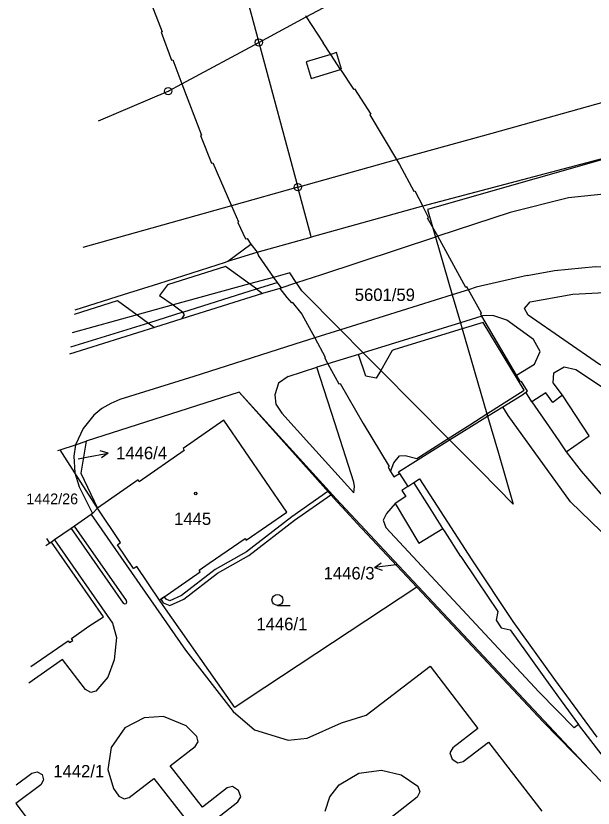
# Model space of a CAD drawing. Extents: x -821458 to -820266, y -1071458 to -1069826.
# Drawn here: x -821457.2 to -821378.4, y -1070339.6 to -1070231.3 of the extents above; entities that cross this region are included whole.
import ezdxf

# ---------------------------------------------------------------- set-up
doc = ezdxf.new("R2010")
doc.units = 0
for name, color, linetype in [('Vrstva 1', 7, 'Continuous'), ('Vrstva 13', 7, 'Continuous'), ('Vrstva 2', 7, 'Continuous'), ('Vrstva 3', 7, 'Continuous'), ('Vrstva 4', 7, 'Continuous'), ('Vrstva 5', 7, 'Continuous'), ('Vrstva 7', 7, 'Continuous'), ('Vrstva 8', 7, 'Continuous')]:
    doc.layers.add(name, color=color, linetype=linetype)

msp = doc.modelspace()

# ---------------------------------------------------------------- linework, layer by layer
at = {"layer": 'Vrstva 1'}
for p, q in [((-821424.05, -1070234.93), (-821418.73, -1070254.7)), ((-821416.94, -1070261.33), (-821418.73, -1070254.7)), ((-821416.89, -1070261.53), (-821416.94, -1070261.33)), ((-821426.75, -1070282.73), (-821447.6, -1070289.43)), ((-821451.51, -1070290.68), (-821451.17, -1070290.58)), ((-821452.56, -1070303.33), (-821453.12, -1070303.73)), ((-821452.36, -1070303.19), (-821452.56, -1070303.33))]:
    msp.add_line(p, q, dxfattribs=at)
for points in [[(-821424.05, -1070234.93), (-821417.57, -1070231.43), (-821414.51, -1070229.78), (-821410.24, -1070227.71), (-821394.03, -1070220.21), (-821378.02, -1070213.44), (-821369.48, -1070209.59), (-821355.16, -1070203.21), (-821343.71, -1070197.56), (-821334.74, -1070193.15), (-821322.52, -1070188.21), (-821304.53, -1070182.89), (-821261.01, -1070170.88), (-821261.33, -1070168.93), (-821259.98, -1070168.07), (-821228.39, -1070159.48), (-821216.2, -1070157.01), (-821161.01, -1070148.33), (-821142.72, -1070147.71), (-821134.77, -1070147.89), (-821110.29, -1070151.09), (-821096.97, -1070153.98), (-821073.33, -1070161.88), (-821060.28, -1070166.43)], [(-821442.06, -1070214.28), (-821435.58, -1070214.52), (-821434.89, -1070214.36), (-821432.44, -1070213.85), (-821429.86, -1070213.34), (-821428.88, -1070216.98), (-821424.05, -1070234.93)], [(-821418.73, -1070254.7), (-821405.24, -1070250.95), (-821392.2, -1070247.33), (-821335.06, -1070231.36)], [(-821445.94, -1070245.65), (-821436.42, -1070241.6), (-821434.54, -1070240.59), (-821424.05, -1070234.93)], [(-821371.34, -1070249.29), (-821401.03, -1070257.75), (-821400.34, -1070260.13), (-821399.93, -1070261.52), (-821397.64, -1070269.41), (-821396.52, -1070273.23), (-821396.28, -1070274.07), (-821392.9, -1070285.68), (-821392.81, -1070286), (-821391.33, -1070291.07), (-821389.31, -1070298), (-821393.74, -1070293.53), (-821398.01, -1070289.23), (-821398.18, -1070289.06), (-821407.41, -1070279.77), (-821409.8, -1070277.36), (-821409.86, -1070277.3), (-821412.91, -1070274.21), (-821418.19, -1070268.87), (-821418.89, -1070267.8), (-821418.94, -1070267.73), (-821419.81, -1070266.41), (-821422.05, -1070267.03), (-821425.31, -1070267.92), (-821435.75, -1070270.8), (-821440.67, -1070272.16), (-821449.52, -1070274.59)], [(-821371.34, -1070249.29), (-821401.67, -1070257.32), (-821402.32, -1070257.49), (-821416.89, -1070261.53)], [(-821418.73, -1070254.7), (-821427.78, -1070257.24), (-821448.08, -1070262.94)], [(-821449.13, -1070271.46), (-821442.52, -1070269.38), (-821437.72, -1070267.88), (-821428.59, -1070264.94), (-821428.28, -1070264.84), (-821424.29, -1070263.58), (-821416.89, -1070261.53)], [(-821402.46, -1070309.37), (-821409.96, -1070301.37), (-821410.07, -1070301.25), (-821412.66, -1070298.44), (-821413.35, -1070297.7), (-821426.75, -1070282.73)], [(-821426.75, -1070282.73), (-821413.5, -1070297.27), (-821402.28, -1070309.25), (-821378.93, -1070334.19)], [(-821437.63, -1070311.14), (-821432.04, -1070307.27), (-821432.21, -1070307.02), (-821430.81, -1070306.06), (-821425.93, -1070302.7), (-821425.76, -1070302.95), (-821420.23, -1070299.1), (-821428.82, -1070286.54), (-821434.39, -1070290.42), (-821434.22, -1070290.67), (-821440.37, -1070294.96), (-821440.54, -1070294.71), (-821446.08, -1070298.58)], [(-821451.17, -1070290.58), (-821449.09, -1070289.91), (-821447.6, -1070289.43)], [(-821447.6, -1070289.43), (-821448.34, -1070293.8), (-821446.08, -1070298.58)], [(-821446.08, -1070298.58), (-821449.17, -1070293.72), (-821451.17, -1070290.58)], [(-821446.08, -1070298.58), (-821446.76, -1070299.3), (-821446.96, -1070299.44), (-821449.22, -1070301.01), (-821449.68, -1070301.33), (-821451.94, -1070302.9), (-821452.36, -1070303.19)], [(-821437.63, -1070311.14), (-821440.72, -1070306.54), (-821441.1, -1070306.79), (-821441.14, -1070306.82), (-821443.34, -1070303.57), (-821443.29, -1070303.53), (-821442.92, -1070303.28), (-821446.08, -1070298.58)], [(-821452.56, -1070303.33), (-821452.99, -1070302.7)], [(-821455.16, -1070320.21), (-821450.09, -1070316.69), (-821449.91, -1070316.94), (-821449.46, -1070316.63), (-821449.64, -1070316.38), (-821447.25, -1070314.71), (-821445.25, -1070313.4), (-821452.36, -1070303.19)], [(-821402.46, -1070309.37), (-821423.23, -1070323.06), (-821426.44, -1070325.19), (-821427.34, -1070325.78), (-821437.11, -1070311.88), (-821437.63, -1070311.14)], [(-821378.93, -1070334.19), (-821385.22, -1070327.77), (-821402.46, -1070309.37)], [(-821309.21, -1070408.41), (-821319.78, -1070397.04), (-821333.24, -1070382.81), (-821356.7, -1070357.89), (-821358.08, -1070356.41), (-821363.03, -1070351.13), (-821378.93, -1070334.19)]]:
    msp.add_lwpolyline(points, dxfattribs=at)
at = {"layer": 'Vrstva 13'}
msp.add_lwpolyline([(-821436.19, -1070311.88), (-821434.3, -1070311.01), (-821429.69, -1070307.46), (-821425.41, -1070305.03), (-821419.16, -1070300.22), (-821414.2, -1070296.75), (-821414.06, -1070296.65), (-821414.47, -1070296.2), (-821414.61, -1070296.3), (-821419.52, -1070299.74), (-821425.75, -1070304.53), (-821430.03, -1070306.96), (-821434.62, -1070310.49), (-821436.19, -1070311.22), (-821436.69, -1070311.01), (-821436.94, -1070310.66), (-821437.43, -1070311), (-821437.09, -1070311.49)], close=True, dxfattribs=at)
at = {"layer": 'Vrstva 3'}
msp.add_line((-821421.5, -1070311.85), (-821419.75, -1070311.85), dxfattribs=at)
msp.add_circle((-821421.5, -1070311.1), 0.75, dxfattribs=at)
at = {"layer": 'Vrstva 4'}
for p, q in [((-821441.18, -1070223.25), (-821437.26, -1070233.48)), ((-821417.69, -1070231.24), (-821417.57, -1070231.43)), ((-821417.57, -1070231.43), (-821415.27, -1070234.99)), ((-821437.26, -1070233.48), (-821437.4, -1070233.54)), ((-821437.4, -1070233.54), (-821435.95, -1070237.35)), ((-821414.24, -1070236.57), (-821415.27, -1070234.99)), ((-821414.24, -1070236.57), (-821417.6, -1070237.6)), ((-821413.44, -1070236.33), (-821414.24, -1070236.57)), ((-821412.89, -1070238.62), (-821414.24, -1070236.57)), ((-821412.75, -1070238.58), (-821413.44, -1070236.33)), ((-821435.95, -1070237.35), (-821435.79, -1070237.32)), ((-821435.79, -1070237.32), (-821434.54, -1070240.59)), ((-821417.6, -1070237.6), (-821416.91, -1070239.85)), ((-821416.91, -1070239.85), (-821412.89, -1070238.62)), ((-821412.89, -1070238.62), (-821412.75, -1070238.58)), ((-821412.89, -1070238.62), (-821411.12, -1070241.34)), ((-821434.54, -1070240.59), (-821431.87, -1070247.59)), ((-821411.12, -1070241.34), (-821410.97, -1070241.27)), ((-821410.97, -1070241.27), (-821408.77, -1070244.74)), ((-821408.77, -1070244.74), (-821408.89, -1070244.82)), ((-821408.89, -1070244.82), (-821405.24, -1070250.95)), ((-821431.87, -1070247.59), (-821432, -1070247.67)), ((-821432, -1070247.67), (-821430.51, -1070251.44)), ((-821405.24, -1070250.95), (-821404.85, -1070251.61)), ((-821430.51, -1070251.44), (-821430.34, -1070251.4)), ((-821430.34, -1070251.4), (-821427.78, -1070257.24)), ((-821404.85, -1070251.61), (-821402.89, -1070255.27)), ((-821402.89, -1070255.27), (-821402.74, -1070255.22)), ((-821402.74, -1070255.22), (-821401.67, -1070257.32)), ((-821427.78, -1070257.24), (-821426.82, -1070259.43)), ((-821426.82, -1070259.43), (-821426.93, -1070259.52)), ((-821426.93, -1070259.52), (-821425.87, -1070261.78)), ((-821399.63, -1070261.42), (-821400.34, -1070260.13)), ((-821425.87, -1070261.78), (-821425.66, -1070261.73)), ((-821425.66, -1070261.73), (-821425.14, -1070262.48)), ((-821399.93, -1070261.52), (-821415.48, -1070266.67)), ((-821399.63, -1070261.42), (-821399.93, -1070261.52)), ((-821395.77, -1070268.41), (-821399.63, -1070261.42)), ((-821428.28, -1070264.84), (-821425.14, -1070262.48)), ((-821425.14, -1070262.48), (-821424.29, -1070263.58)), ((-821422.05, -1070267.03), (-821421.56, -1070267.74)), ((-821415.48, -1070266.67), (-821418.89, -1070267.8)), ((-821424.35, -1070268.62), (-821425.31, -1070267.92)), ((-821424.35, -1070268.62), (-821421.56, -1070267.74)), ((-821418.89, -1070267.8), (-821421.18, -1070268.56)), ((-821437.59, -1070269.49), (-821435.75, -1070270.8)), ((-821423.53, -1070269.22), (-821434.55, -1070272.69)), ((-821434.42, -1070271.8), (-821424.35, -1070268.62)), ((-821424.35, -1070268.62), (-821423.53, -1070269.22)), ((-821421.18, -1070268.56), (-821423.53, -1070269.22)), ((-821397.64, -1070269.41), (-821409.27, -1070273.07)), ((-821395.43, -1070268.72), (-821397.64, -1070269.41)), ((-821449.2, -1070272.06), (-821443.34, -1070270.21)), ((-821443.34, -1070270.21), (-821440.67, -1070272.16)), ((-821435.75, -1070270.8), (-821434.47, -1070271.72)), ((-821440.67, -1070272.16), (-821439.12, -1070273.29)), ((-821434.42, -1070271.8), (-821439.12, -1070273.29)), ((-821434.55, -1070272.69), (-821438.31, -1070273.88)), ((-821434.42, -1070271.8), (-821434.47, -1070271.72)), ((-821393.6, -1070272.33), (-821396.52, -1070273.23)), ((-821393.51, -1070272.3), (-821393.6, -1070272.33)), ((-821388.88, -1070280.39), (-821393.6, -1070272.33)), ((-821438.31, -1070273.88), (-821449.88, -1070277.52)), ((-821439.12, -1070273.29), (-821449.76, -1070276.58)), ((-821439.12, -1070273.29), (-821438.31, -1070273.88)), ((-821409.27, -1070273.07), (-821412.91, -1070274.21)), ((-821396.52, -1070273.23), (-821406.13, -1070276.22)), ((-821393.4, -1070273.19), (-821396.28, -1070274.07)), ((-821387.81, -1070282.43), (-821393.4, -1070273.19)), ((-821412.91, -1070274.21), (-821416.41, -1070275.31)), ((-821396.28, -1070274.07), (-821405.46, -1070276.9)), ((-821406.13, -1070276.22), (-821409.8, -1070277.36)), ((-821405.83, -1070277.01), (-821407.41, -1070279.77)), ((-821405.46, -1070276.9), (-821405.83, -1070277.01)), ((-821410.46, -1070277.57), (-821414.63, -1070278.85)), ((-821409.8, -1070277.36), (-821410.46, -1070277.57)), ((-821409.42, -1070280.53), (-821410.46, -1070277.57)), ((-821414.63, -1070278.85), (-821416.15, -1070279.32)), ((-821414.64, -1070278.84), (-821414.63, -1070278.85)), ((-821414.63, -1070278.85), (-821413.11, -1070281.58)), ((-821420.04, -1070280.57), (-821416.15, -1070279.32)), ((-821407.41, -1070279.77), (-821408.01, -1070280.82)), ((-821408.01, -1070280.82), (-821409.42, -1070280.53)), ((-821392.9, -1070285.68), (-821387.81, -1070282.43)), ((-821390.73, -1070284.71), (-821388.16, -1070283.11)), ((-821388.16, -1070283.11), (-821387.61, -1070282.74)), ((-821386.79, -1070284.04), (-821387.61, -1070282.74)), ((-821395.22, -1070287.17), (-821392.9, -1070285.68)), ((-821392.81, -1070286), (-821390.73, -1070284.71)), ((-821395.02, -1070287.37), (-821392.81, -1070286)), ((-821398.18, -1070289.06), (-821395.22, -1070287.17)), ((-821398.01, -1070289.23), (-821395.02, -1070287.37)), ((-821405, -1070293.58), (-821398.01, -1070289.23)), ((-821402.48, -1070291.8), (-821398.18, -1070289.06)), ((-821405.6, -1070292.38), (-821404.83, -1070291.43)), ((-821404.83, -1070291.43), (-821404.06, -1070291.38)), ((-821404.06, -1070291.38), (-821402.48, -1070291.8)), ((-821406.05, -1070293.56), (-821405.6, -1070292.38)), ((-821404.83, -1070293.83), (-821405, -1070293.58)), ((-821404.83, -1070293.83), (-821403.71, -1070295.61)), ((-821403.71, -1070295.61), (-821402.87, -1070295.08)), ((-821446.96, -1070299.44), (-821434.04, -1070317.95)), ((-821449.68, -1070301.33), (-821442.57, -1070311.53)), ((-821442.1, -1070311.2), (-821449.22, -1070301.01)), ((-821451.94, -1070302.9), (-821444.01, -1070314.26)), ((-821442.57, -1070311.53), (-821442.38, -1070311.64)), ((-821442.38, -1070311.64), (-821442.17, -1070311.6)), ((-821442.17, -1070311.6), (-821442.05, -1070311.41)), ((-821442.05, -1070311.41), (-821442.1, -1070311.2)), ((-821444.01, -1070314.26), (-821443.49, -1070316.22)), ((-821443.49, -1070316.22), (-821443.78, -1070319.27)), ((-821434.04, -1070317.95), (-821427.57, -1070326.33)), ((-821450.85, -1070319.26), (-821455.44, -1070322.46)), ((-821447.69, -1070323.35), (-821450.85, -1070319.26)), ((-821443.78, -1070319.27), (-821444.65, -1070321.65)), ((-821409.39, -1070326.84), (-821400.65, -1070320.16)), ((-821400.65, -1070320.16), (-821394.14, -1070328.65)), ((-821444.65, -1070321.65), (-821446.28, -1070323.55)), ((-821447, -1070323.75), (-821447.69, -1070323.35)), ((-821446.28, -1070323.55), (-821447, -1070323.75)), ((-821427.57, -1070326.33), (-821424.65, -1070328.87)), ((-821412.74, -1070327.91), (-821409.39, -1070326.84)), ((-821439.7, -1070327.22), (-821442.33, -1070328.6)), ((-821437.05, -1070327.03), (-821439.7, -1070327.22)), ((-821433.95, -1070328.29), (-821437.05, -1070327.03)), ((-821417.46, -1070330), (-821412.74, -1070327.91)), ((-821442.33, -1070328.6), (-821444.23, -1070331.29)), ((-821432.53, -1070329.75), (-821433.95, -1070328.29)), ((-821424.65, -1070328.87), (-821420.06, -1070330.28)), ((-821394.14, -1070328.65), (-821397.58, -1070331.31)), ((-821432.34, -1070330.49), (-821432.53, -1070329.75)), ((-821420.06, -1070330.28), (-821417.46, -1070330)), ((-821436.13, -1070333.78), (-821432.72, -1070331.14)), ((-821432.72, -1070331.14), (-821432.34, -1070330.49)), ((-821396.15, -1070333.17), (-821392.69, -1070330.53)), ((-821392.69, -1070330.53), (-821385.41, -1070339.97)), ((-821444.23, -1070331.29), (-821444.68, -1070334.26)), ((-821397.58, -1070331.31), (-821397.96, -1070331.98)), ((-821397.96, -1070331.98), (-821397.65, -1070332.85)), ((-821397.65, -1070332.85), (-821396.88, -1070333.37)), ((-821396.88, -1070333.37), (-821396.15, -1070333.17)), ((-821444.68, -1070334.26), (-821443.89, -1070336.85)), ((-821431.75, -1070339.42), (-821436.13, -1070333.78)), ((-821410.39, -1070334.78), (-821407.31, -1070334.37)), ((-821407.31, -1070334.37), (-821404.61, -1070334.98)), ((-821457.16, -1070336.37), (-821455.04, -1070334.77)), ((-821455.04, -1070334.77), (-821454.3, -1070334.57)), ((-821454.3, -1070334.57), (-821453.63, -1070334.95)), ((-821453.63, -1070334.95), (-821453.44, -1070335.7)), ((-821441.73, -1070338.08), (-821438.36, -1070335.49)), ((-821438.36, -1070335.49), (-821433.98, -1070341.14)), ((-821413.07, -1070336.37), (-821410.39, -1070334.78)), ((-821404.61, -1070334.98), (-821402.33, -1070336.55)), ((-821453.83, -1070336.35), (-821457.22, -1070338.94)), ((-821453.44, -1070335.7), (-821453.83, -1070336.35)), ((-821427.63, -1070336.58), (-821428.39, -1070336.8)), ((-821426.83, -1070337.13), (-821427.63, -1070336.58)), ((-821414.35, -1070337.99), (-821413.07, -1070336.37)), ((-821402.33, -1070336.55), (-821402.05, -1070337.32)), ((-821443.89, -1070336.85), (-821443.14, -1070337.9)), ((-821428.39, -1070336.8), (-821431.75, -1070339.42)), ((-821426.52, -1070338.02), (-821426.83, -1070337.13)), ((-821402.05, -1070337.32), (-821402.43, -1070338.04)), ((-821443.14, -1070337.9), (-821442.44, -1070338.29)), ((-821442.44, -1070338.29), (-821441.73, -1070338.08)), ((-821430.29, -1070341.32), (-821426.91, -1070338.7)), ((-821426.91, -1070338.7), (-821426.52, -1070338.02)), ((-821414.99, -1070339.96), (-821414.35, -1070337.99)), ((-821402.43, -1070338.04), (-821405.82, -1070340.68)), ((-821457.22, -1070338.94), (-821454.32, -1070342.74))]:
    msp.add_line(p, q, dxfattribs=at)
for points in [[(-821342.86, -1070268.96), (-821348.96, -1070263), (-821358.79, -1070257.48), (-821371.24, -1070255.06), (-821381.79, -1070256.18), (-821389.72, -1070258.19), (-821399.63, -1070261.42)], [(-821400.34, -1070260.13), (-821401, -1070258.93), (-821400.87, -1070258.87), (-821401.39, -1070257.85), (-821401.67, -1070257.32)], [(-821424.29, -1070263.58), (-821424.08, -1070264.1), (-821422.05, -1070267.03)], [(-821425.31, -1070267.92), (-821428.59, -1070265.53), (-821436.52, -1070268.04), (-821437.59, -1070269.49)], [(-821387.43, -1070266.76), (-821383.68, -1070266.08), (-821378.08, -1070265.55), (-821368.86, -1070265.95), (-821360.73, -1070268.5), (-821350.71, -1070276.26)], [(-821387.43, -1070266.76), (-821394.36, -1070268.38), (-821395.43, -1070268.72)], [(-821421.56, -1070267.74), (-821421.05, -1070268.41), (-821421.18, -1070268.56)], [(-821395.43, -1070268.72), (-821395.64, -1070268.34), (-821395.77, -1070268.41)], [(-821421.18, -1070268.56), (-821420.21, -1070269.78), (-821419.61, -1070270.53), (-821419.48, -1070270.43), (-821418.19, -1070272.06), (-821416.41, -1070275.31)], [(-821393.6, -1070272.33), (-821393.78, -1070272.02), (-821393.66, -1070271.93), (-821395.43, -1070268.72)], [(-821376.09, -1070278.75), (-821376.72, -1070279.24), (-821377.52, -1070278.96), (-821387.29, -1070272.19), (-821387.78, -1070271.28), (-821387.02, -1070270.36), (-821381.2, -1070269.32), (-821376, -1070269.05), (-821372.37, -1070269.11), (-821371.47, -1070269.77), (-821371.58, -1070271.03), (-821374.3, -1070275.69), (-821376.09, -1070278.75)], [(-821434.55, -1070272.69), (-821434.19, -1070272.15), (-821434.42, -1070271.8)], [(-821388.88, -1070280.39), (-821386.43, -1070278.88), (-821385.65, -1070277.18), (-821386.53, -1070275.5), (-821390.18, -1070272.86), (-821392.09, -1070272.26), (-821393.51, -1070272.3)], [(-821416.41, -1070275.31), (-821419.13, -1070276.17), (-821429.64, -1070279.51), (-821432.94, -1070280.56), (-821443.02, -1070283.73), (-821444.27, -1070284.27), (-821445.46, -1070284.95), (-821446.59, -1070285.88), (-821448.05, -1070287.7), (-821449.09, -1070289.91)], [(-821416.41, -1070275.31), (-821414.99, -1070277.92), (-821415.1, -1070278), (-821414.64, -1070278.84)], [(-821382.6, -1070283.15), (-821383.87, -1070281.44), (-821383.79, -1070280.09), (-821382.36, -1070279.25), (-821380.79, -1070279.62), (-821374.94, -1070283.47), (-821361.39, -1070293.07), (-821357.57, -1070296.01), (-821354.03, -1070299.5)], [(-821420.04, -1070280.57), (-821421.37, -1070281.5), (-821421.87, -1070283.08), (-821421.72, -1070284.35), (-821420.92, -1070285.57), (-821417.12, -1070289.79), (-821411.09, -1070296.45), (-821410.97, -1070295.6), (-821411.07, -1070295), (-821413.67, -1070286.9), (-821416.15, -1070279.32)], [(-821387.61, -1070282.74), (-821387.38, -1070282.59), (-821388.18, -1070281.25), (-821388.32, -1070281.3), (-821388.88, -1070280.39)], [(-821413.11, -1070281.58), (-821412.96, -1070281.52), (-821409.79, -1070287.02), (-821406.27, -1070292.86), (-821406.4, -1070292.97), (-821406.05, -1070293.56)], [(-821382.6, -1070283.15), (-821383.92, -1070284.13), (-821384.86, -1070282.79), (-821386.79, -1070284.04)], [(-821382.07, -1070290.86), (-821378.94, -1070288.7), (-821382.6, -1070283.15)], [(-821386.79, -1070284.04), (-821384.43, -1070287.45), (-821383.11, -1070289.35), (-821382.07, -1070290.86)], [(-821351.55, -1070301.65), (-821355.43, -1070305.31), (-821362.37, -1070307.43), (-821367.16, -1070307.31), (-821374.57, -1070304.4), (-821381.51, -1070297.69), (-821389.99, -1070285.91), (-821390.73, -1070284.71)], [(-821449.09, -1070289.91), (-821449.3, -1070291.44), (-821449.17, -1070293.72)], [(-821382.07, -1070290.86), (-821380.02, -1070293.53), (-821377.44, -1070296.54), (-821376.84, -1070297.09), (-821375.59, -1070297.11), (-821374.76, -1070298), (-821374.77, -1070299.32), (-821371.79, -1070301.66), (-821368.28, -1070303.14), (-821364.62, -1070303.71), (-821362.7, -1070304), (-821360.72, -1070303.29), (-821360.3, -1070302.15), (-821359.16, -1070301.74), (-821358.02, -1070302.29), (-821357.33, -1070301.98), (-821354.25, -1070299.78), (-821354.03, -1070299.5)], [(-821449.17, -1070293.72), (-821448.59, -1070295.67), (-821446.76, -1070299.3)], [(-821406.05, -1070293.56), (-821405.6, -1070294.3), (-821404.83, -1070293.83)], [(-821402.87, -1070295.08), (-821402.11, -1070294.58), (-821394.96, -1070305.62)], [(-821398.91, -1070301.33), (-821400.75, -1070298.43), (-821402.87, -1070295.08)], [(-821403.71, -1070295.61), (-821404.53, -1070296.14), (-821403.99, -1070296.96), (-821405.42, -1070297.93)], [(-821405.42, -1070297.93), (-821406.64, -1070299.28), (-821407.09, -1070300.21), (-821406.69, -1070301.2), (-821385.79, -1070323.73)], [(-821405.42, -1070297.93), (-821402.19, -1070303.35), (-821398.91, -1070301.33)], [(-821396.45, -1070305.15), (-821398.61, -1070301.8), (-821398.91, -1070301.33)], [(-821396.45, -1070305.15), (-821394.22, -1070308.48), (-821391.42, -1070312.67), (-821391.65, -1070313.89), (-821390.95, -1070314.92), (-821389.73, -1070315.21), (-821387.4, -1070318.43), (-821385.12, -1070321.61), (-821382.75, -1070324.89), (-821380.39, -1070328.11)], [(-821394.96, -1070305.62), (-821389.36, -1070314.05), (-821383.69, -1070321.98), (-821377.88, -1070329.85)], [(-821380.39, -1070328.11), (-821380.98, -1070328.58), (-821385.79, -1070323.73)], [(-821370.15, -1070339.69), (-821370.9, -1070340.19), (-821373.42, -1070337.09), (-821375.55, -1070334.41), (-821377.96, -1070331.31), (-821380.39, -1070328.11)]]:
    msp.add_lwpolyline(points, dxfattribs=at)
at = {"layer": 'Vrstva 5'}
msp.add_circle((-821432.67, -1070296.56), 0.175, dxfattribs=at)
at = {"layer": 'Vrstva 7'}
for p, q in [((-821447.59, -1070291.6), (-821444.64, -1070291.03)), ((-821444.64, -1070291.03), (-821445.72, -1070290.73)), ((-821444.64, -1070291.03), (-821445.53, -1070291.71)), ((-821448.71, -1070291.82), (-821447.59, -1070291.6)), ((-821408.27, -1070306.66), (-821407.34, -1070306.04)), ((-821405.29, -1070306.29), (-821408.27, -1070306.66)), ((-821405.21, -1070306.28), (-821405.29, -1070306.29)), ((-821408.27, -1070306.66), (-821407.21, -1070307.03))]:
    msp.add_line(p, q, dxfattribs=at)
at = {"layer": 'Vrstva 8'}
for centre, radius in [((-821424.05, -1070234.93), 0.5), ((-821424.05, -1070234.93), 0.0303), ((-821436.42, -1070241.6), 0.5), ((-821436.42, -1070241.6), 0.0303), ((-821418.73, -1070254.7), 0.5), ((-821418.73, -1070254.7), 0.0303)]:
    msp.add_circle(centre, radius, dxfattribs=at)

# ---------------------------------------------------------------- texts
at = {"layer": 'Vrstva 2'}
for s, height, p in [('5601/59', 1.7, (-821410.95, -1070270.26)), ('1446/4', 1.7, (-821443.53, -1070291.88)), ('1442/26', 1.465, (-821455.8, -1070298.03)), ('1445', 1.7, (-821435.61, -1070300.86)), ('1446/3', 1.7, (-821415.2, -1070308.3)), ('1446/1', 1.7, (-821424.38, -1070315.24)), ('1442/1', 1.7, (-821452.11, -1070335.36))]:
    msp.add_text(s, height=height, dxfattribs=at).set_placement(p)

doc.saveas('drawing.dxf')
